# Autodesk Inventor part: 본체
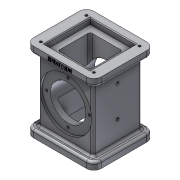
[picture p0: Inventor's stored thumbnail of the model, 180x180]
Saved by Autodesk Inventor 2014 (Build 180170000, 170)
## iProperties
Created: 2017-08
Part Number: 본체
Material: Aluminum 6061
Document SubType Name: Modeling
Designer: user
Density: 2.71 g/cm^3
Appearance: Aluminum - Flat
Mass: 810.055 g
Surface Area: 619.348 cm^2
Volume: 298.913 cm^3
Author: user
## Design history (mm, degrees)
sketch "Sketch1"
  geometry: L1 (-46, 41)-(46, 41); L2 (46, 41)-(46, -41); L3 (46, -41)-(-46, -41); L4 (-46, -41)-(-46, 41); L5 (-46, 41)-(46, -41); L6 (46, 41)-(-46, -41); 1 further point
  constraints: 12 end point, 2 midpoint, 2 parallel, 1 horizontal, 1 perpendicular
  dimensions: "d0" = 92 distance of L1.start L1.end; "d1" = 82 distance of L1.end L2.end
extrude "Extrusion1" new body sketch "Sketch1" distance "d2" = 10; taper "d3" = 0 deg
sketch "Sketch2"
  geometry: L1 (-37, 33)-(37, 33); L2 (37, 33)-(37, -33); L3 (37, -33)-(-37, -33); L4 (-37, -33)-(-37, 33); L5 (-37, 33)-(37, -33); L6 (37, 33)-(-37, -33); 1 further point
  constraints: 12 end point, 2 midpoint, 2 parallel, 1 horizontal, 1 perpendicular
  dimensions: "d12" = 74 distance of L2.end L3.end; "d13" = 66 distance of L1.end L2.end
extrude "Extrusion2" join sketch "Sketch2" distance "d5" = 88; taper "d6" = 0 deg
sketch "Sketch3"
  geometry: L1 (-46, 41)-(46, 41); L2 (46, 41)-(46, -41); L3 (46, -41)-(-46, -41); L4 (-46, -41)-(-46, 41); L5 (-46, 41)-(46, -41); L6 (46, 41)-(-46, -41); 1 further point
  constraints: 12 end point, 2 midpoint, 2 parallel, 1 horizontal, 1 perpendicular
  dimensions: "d7" = 82 distance of L1.end L2.end; "d8" = 92 distance of L2.end L3.end
extrude "Extrusion3" join sketch "Sketch3" distance "d9" = 10; taper "d10" = 0 deg
sketch "Sketch4"
  geometry: L1 (-22, 22)-(22, 22); L2 (22, 22)-(22, -22); L3 (22, -22)-(-22, -22); L4 (-22, -22)-(-22, 22); L5 (-22, 22)-(22, -22); L6 (22, 22)-(-22, -22); 1 further point
  constraints: 12 end point, 2 midpoint, 2 parallel, 1 horizontal, 1 perpendicular
  dimensions: "d14" = 44 distance of L2.end L3.end; "d15" = 44 distance of L1.end L2.end
extrude "Extrusion4" cut sketch "Sketch4" stored distance "d16" = 10; taper "d17" = 0 deg
sketch "Sketch6"
  geometry: L1 (83, -10)-(-9, -10) reference; C1 r 24 at (37, 44); 2 further points
  constraints: 1 centre point, 1 midpoint, 1 vertical alignment
  dimensions: "d18" = 48 diameter of C1; "d19" = 54 distance from line of L1 C1.centre
extrude "Extrusion5" cut sketch "Sketch6" stored distance "d20" = 10; taper "d21" = 0 deg
sketch "Sketch7"
  geometry: L1 (-24, 24)-(24, 24); L2 (24, 24)-(24, -24); L3 (24, -24)-(-24, -24); L4 (-24, -24)-(-24, 24); L5 (-24, 24)-(24, -24); L6 (24, 24)-(-24, -24); 1 further point
  constraints: 12 end point, 2 midpoint, 2 parallel, 1 horizontal, 1 perpendicular
  dimensions: "d22" = 48 distance of L2.end L3.end; "d23" = 48 distance of L1.end L2.end
extrude "Extrusion6" cut sketch "Sketch7" distance "d24" = 16; taper "d25" = 0 deg
sketch "Sketch8"
  geometry: C1 r 24 at (37, 44) reference; C2 r 35 at (37, 44); 1 further point
  constraints: 1 centre point, 1 coincident
  dimensions: "d26" = 70 diameter of C2
extrude "Extrusion7" cut sketch "Sketch8" distance "d27" = 3; taper "d28" = 0 deg
mirror "Mirror1"
sketch "Sketch9"
  geometry: L1 (0, 0)-(0, 29); C1 r 35 at (0, 0) reference; 1 further point
  constraints: 2 end point, 1 vertical
  dimensions: "d29" = 29 distance of L1.start L1.end
hole "Hole1" sketch "Sketch9" at (0, 29) diameter "d30" = 3.242; stored, may be unused: countersink angle "d34" = 90 deg, drill point angle "d36" = 118 deg; dims "d31" = 4, "d32" = 4, "d33" = 2, "d35" = 6
pattern_circular "Circular Pattern1" dims angle "d38" = 360 deg
mirror "Mirror2"
sketch "Sketch10"
  geometry: L1 (-36, 31)-(36, 31); L2 (36, 31)-(36, -31); L3 (36, -31)-(-36, -31); L4 (-36, -31)-(-36, 31); L5 (-36, 31)-(36, -31); L6 (36, 31)-(-36, -31); 2 further points
  constraints: 12 end point, 2 midpoint, 2 parallel, 1 coincident, 1 horizontal, 1 perpendicular
  dimensions: "d40" = 62 distance of L1.end L2.end; "d41" = 72 distance of L1.start L1.end
hole "Hole2" sketch "Sketch10" at (36, -31) diameter "d42" = 3.242; stored, may be unused: countersink angle "d46" = 90 deg, drill point angle "d48" = 118 deg; dims "d43" = 4, "d44" = 4, "d45" = 2, "d47" = 6
mirror "Mirror3"
mirror "Mirror4"
sketch "Sketch11"
  geometry: L1 (-36, 31)-(36, 31); L2 (36, 31)-(36, -31); L3 (36, -31)-(-36, -31); L4 (-36, -31)-(-36, 31); L5 (-36, 31)-(36, -31); L6 (36, 31)-(-36, -31); 2 further points
  constraints: 12 end point, 2 midpoint, 2 parallel, 1 coincident, 1 horizontal, 1 perpendicular
  dimensions: "d49" = 62 distance of L1.end L2.end; "d50" = 72 distance of L1.start L1.end
hole "Hole3" sketch "Sketch11" at (36, -31) diameter "d51" = 3.242; stored, may be unused: countersink angle "d55" = 90 deg, drill point angle "d57" = 118 deg; dims "d52" = 4, "d53" = 4, "d54" = 2, "d56" = 6
mirror "Mirror5"
mirror "Mirror6"
fillet "Fillet1" dims "d58" = 10
fillet "Fillet2" dims "d59" = 3
fillet "Fillet3" dims "d60" = 3
fillet "Fillet4" dims "d61" = 3
fillet "Fillet5" dims "d62" = 3
sketch "Sketch12"
  geometry: L1 (61, -13)-(-1, -13) reference; 5 further points
  constraints: 2 midpoint, 2 vertical alignment
  dimensions: "d63" = 38 distance from line of point (30, 25) L1; "d64" = 42 distance of point (30, 67) point (30, 25)
hole "Hole4" sketch "Sketch12" at (30, 25), (30, 67) diameter "d65" = 4.134; stored, may be unused: countersink angle "d69" = 90 deg, drill point angle "d71" = 0 deg; dims "d66" = 4, "d67" = 4, "d68" = 2, "d70" = 6
sketch "Sketch13"
  geometry: L1 (-10, 0)-(-10, -7) reference; L2 (72, 0)-(82, 0) reference; 2 further points
  constraints: 1 other
  dimensions: "d72" = 46 distance from line of point (36, -4) L1; "d73" = 4 distance from line of point (36, -4) L2
emboss "Emboss1" sketch "Sketch13" dims "d0" = 92, "d1" = 82, "d74" = 0.5, "d75" = 0
chamfer "Chamfer1" distance "d76" = 1; stored, may be unused: second distance "d77" = 2, angle "d78" = 45 deg
sketch "Sketch14"
  geometry: L1 (-31, 31)-(31, 31); L2 (31, 31)-(31, -31); L3 (31, -31)-(-31, -31); L4 (-31, -31)-(-31, 31); L5 (-31, 31)-(31, -31); L6 (31, 31)-(-31, -31); 1 further point
  constraints: 12 end point, 2 midpoint, 2 parallel, 1 horizontal, 1 perpendicular
  dimensions: "d79" = 62 distance of L1.end L2.end; "d80" = 62 distance of L2.end L3.end
extrude "Extrusion8" cut sketch "Sketch14" distance "d81" = 8; taper "d82" = 0 deg
chamfer "Chamfer2" distance "d83" = 1; stored, may be unused: second distance "d84" = 2, angle "d85" = 45 deg
body "Solid1"
